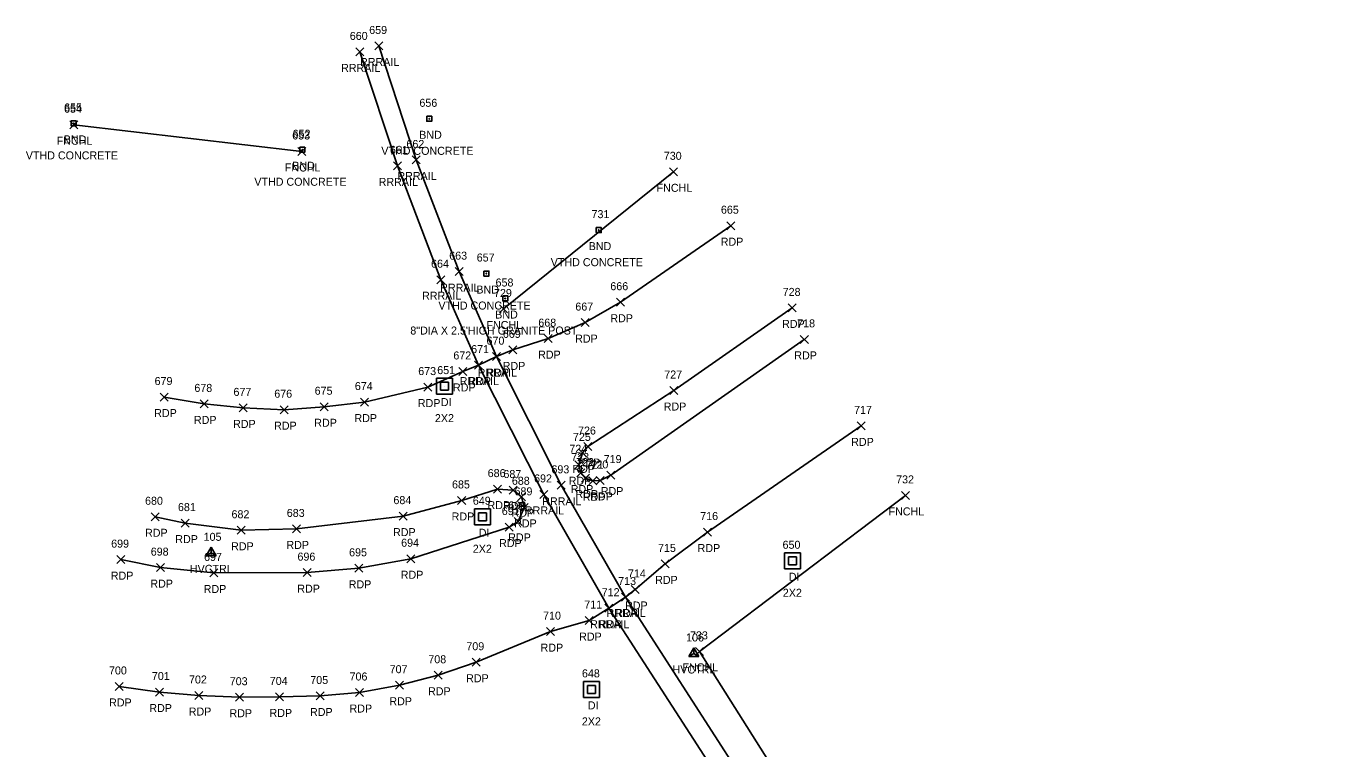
# Model space of a CAD drawing. Extents: x 1638029 to 1638889, y 618768 to 620505.
# Drawn here: x 1638029 to 1638352.1, y 620324.6 to 620505.1 of the extents above; entities that cross this region are included whole.
import ezdxf

# ---------------------------------------------------------------- set-up
doc = ezdxf.new("R2010")
doc.units = 0
for name, color, linetype in [('C_A', 7, 'Continuous'), ('C_I', 7, 'Continuous'), ('CPSM', 7, 'Continuous'), ('D_A', 7, 'Continuous'), ('D_C', 7, 'Continuous'), ('D_I', 7, 'Continuous'), ('DS', 7, 'Continuous'), ('L_A', 7, 'Continuous'), ('L_I', 7, 'Continuous'), ('L_TIC', 7, 'Continuous'), ('LFNC', 7, 'Continuous'), ('M_A', 7, 'Continuous'), ('M_C', 7, 'Continuous'), ('M_I', 7, 'Continuous'), ('MHBP', 7, 'Continuous'), ('P_A', 7, 'Continuous'), ('P_I', 7, 'Continuous'), ('P_TIC', 7, 'Continuous'), ('PET', 7, 'Continuous'), ('R_A', 7, 'Continuous'), ('R_I', 7, 'Continuous'), ('R_TIC', 7, 'Continuous'), ('RR', 7, 'Continuous')]:
    doc.layers.add(name, color=color, linetype=linetype)

msp = doc.modelspace()

# ---------------------------------------------------------------- linework, layer by layer
at = {"layer": 'CPSM'}
for p, q in [((1638074.04, 620372.66), (1638075.29, 620374.82)), ((1638074.04, 620372.66), (1638075.29, 620373.38)), ((1638076.54, 620372.66), (1638075.29, 620374.82)), ((1638075.29, 620373.38), (1638075.29, 620374.82)), ((1638075.29, 620373.38), (1638075.29, 620373.38)), ((1638075.29, 620373.38), (1638076.54, 620372.66)), ((1638074.04, 620372.66), (1638076.54, 620372.66)), ((1638194.63, 620347.51), (1638195.88, 620349.68)), ((1638194.63, 620347.51), (1638195.88, 620348.23)), ((1638194.63, 620347.51), (1638197.13, 620347.51)), ((1638197.13, 620347.51), (1638195.88, 620349.68)), ((1638195.88, 620348.23), (1638195.88, 620349.68)), ((1638195.88, 620348.23), (1638195.88, 620348.23)), ((1638195.88, 620348.23), (1638197.13, 620347.51))]:
    msp.add_line(p, q, dxfattribs=at)
at = {"layer": 'DS'}
for p, q in [((1638131.61, 620417.03), (1638135.61, 620417.03)), ((1638131.61, 620413.03), (1638131.61, 620417.03)), ((1638132.61, 620414.03), (1638132.61, 620416.03)), ((1638132.61, 620416.03), (1638134.61, 620416.03)), ((1638133.61, 620415.04), (1638133.61, 620415.04)), ((1638133.61, 620415.04), (1638133.61, 620415.04)), ((1638134.61, 620416.03), (1638134.61, 620414.03)), ((1638135.61, 620417.03), (1638135.61, 620413.03)), ((1638135.61, 620413.03), (1638131.61, 620413.03)), ((1638134.61, 620414.03), (1638132.61, 620414.03)), ((1638141.08, 620384.4), (1638145.08, 620384.4)), ((1638141.08, 620380.4), (1638141.08, 620384.4)), ((1638142.08, 620381.4), (1638142.08, 620383.4)), ((1638142.08, 620383.4), (1638144.08, 620383.4)), ((1638144.08, 620383.4), (1638144.08, 620381.4)), ((1638145.08, 620384.4), (1638145.08, 620380.4)), ((1638145.08, 620380.4), (1638141.08, 620380.4)), ((1638144.08, 620381.4), (1638142.08, 620381.4)), ((1638143.09, 620382.4), (1638143.09, 620382.4)), ((1638143.09, 620382.4), (1638143.09, 620382.4)), ((1638218.54, 620373.4), (1638222.54, 620373.4)), ((1638218.54, 620369.4), (1638218.54, 620373.4)), ((1638222.54, 620373.4), (1638222.54, 620369.4)), ((1638219.54, 620370.4), (1638219.54, 620372.4)), ((1638219.54, 620372.4), (1638221.54, 620372.4)), ((1638221.54, 620370.4), (1638219.54, 620370.4)), ((1638220.55, 620371.4), (1638220.55, 620371.4)), ((1638220.55, 620371.4), (1638220.55, 620371.4)), ((1638221.54, 620372.4), (1638221.54, 620370.4)), ((1638222.54, 620369.4), (1638218.54, 620369.4)), ((1638168.33, 620341.26), (1638172.33, 620341.26)), ((1638168.33, 620337.26), (1638168.33, 620341.26)), ((1638172.33, 620341.26), (1638172.33, 620337.26)), ((1638169.33, 620338.26), (1638169.33, 620340.26)), ((1638169.33, 620340.26), (1638171.33, 620340.26)), ((1638171.33, 620338.26), (1638169.33, 620338.26)), ((1638170.34, 620339.26), (1638170.34, 620339.26)), ((1638170.34, 620339.26), (1638170.34, 620339.26)), ((1638171.33, 620340.26), (1638171.33, 620338.26)), ((1638172.33, 620337.26), (1638168.33, 620337.26))]:
    msp.add_line(p, q, dxfattribs=at)
at = {"layer": 'L_TIC'}
for points in [[(1638039.95, 620479.35), (1638041.95, 620481.35)], [(1638041.95, 620479.35), (1638039.95, 620481.35)], [(1638096.95, 620472.67), (1638098.95, 620474.67)], [(1638098.95, 620472.67), (1638096.95, 620474.67)], [(1638189.83, 620467.59), (1638191.83, 620469.59)], [(1638191.83, 620467.59), (1638189.83, 620469.59)], [(1638147.32, 620433.31), (1638149.32, 620435.31)], [(1638149.32, 620433.31), (1638147.32, 620435.31)], [(1638247.78, 620386.73), (1638249.78, 620388.73)], [(1638249.78, 620386.73), (1638247.78, 620388.73)], [(1638196.3, 620347.76), (1638198.3, 620349.76)], [(1638198.3, 620347.76), (1638196.3, 620349.76)]]:
    msp.add_lwpolyline(points, dxfattribs=at)
at = {"layer": 'LFNC'}
for points in [[(1638097.95, 620473.67), (1638040.95, 620480.35)], [(1638148.32, 620434.31), (1638190.83, 620468.59)], [(1638248.78, 620387.73), (1638197.3, 620348.76), (1638216.93, 620317.58)]]:
    msp.add_lwpolyline(points, dxfattribs=at)
at = {"layer": 'MHBP'}
for points in [[(1638040.35, 620481.32), (1638041.6, 620481.32), (1638041.6, 620480.07), (1638040.35, 620480.07)], [(1638129.16, 620482.46), (1638130.41, 620482.46), (1638130.41, 620481.21), (1638129.16, 620481.21)], [(1638097.44, 620474.73), (1638098.69, 620474.73), (1638098.69, 620473.48), (1638097.44, 620473.48)], [(1638171.49, 620454.64), (1638172.74, 620454.64), (1638172.74, 620453.39), (1638171.49, 620453.39)], [(1638143.43, 620443.79), (1638144.68, 620443.79), (1638144.68, 620442.54), (1638143.43, 620442.54)], [(1638148.13, 620437.56), (1638149.38, 620437.56), (1638149.38, 620436.31), (1638148.13, 620436.31)]]:
    msp.add_lwpolyline(points, close=True, dxfattribs=at)
for centre in [(1638040.97, 620480.69), (1638129.78, 620481.83), (1638098.06, 620474.1), (1638172.12, 620454.01), (1638144.05, 620443.17), (1638148.76, 620436.93)]:
    msp.add_circle(centre, 0.0833, dxfattribs=at)
at = {"layer": 'P_TIC'}
for points in [[(1638204.11, 620454.12), (1638206.11, 620456.12)], [(1638206.11, 620454.12), (1638204.11, 620456.12)], [(1638176.53, 620435), (1638178.53, 620437)], [(1638178.53, 620435), (1638176.53, 620437)], [(1638219.44, 620433.58), (1638221.44, 620435.58)], [(1638221.44, 620433.58), (1638219.44, 620435.58)], [(1638167.74, 620429.91), (1638169.74, 620431.91)], [(1638169.74, 620429.91), (1638167.74, 620431.91)], [(1638158.49, 620425.9), (1638160.49, 620427.9)], [(1638160.49, 620425.9), (1638158.49, 620427.9)], [(1638149.63, 620423.09), (1638151.63, 620425.09)], [(1638151.63, 620423.09), (1638149.63, 620425.09)], [(1638222.49, 620425.72), (1638224.49, 620427.72)], [(1638224.49, 620425.72), (1638222.49, 620427.72)], [(1638145.58, 620421.4), (1638147.58, 620423.4)], [(1638147.58, 620421.4), (1638145.58, 620423.4)], [(1638137.21, 620417.7), (1638139.21, 620419.7)], [(1638139.21, 620417.7), (1638137.21, 620419.7)], [(1638141.09, 620419.29), (1638143.09, 620421.29)], [(1638143.09, 620419.29), (1638141.09, 620421.29)], [(1638128.44, 620413.8), (1638130.44, 620415.8)], [(1638130.44, 620413.8), (1638128.44, 620415.8)], [(1638189.86, 620412.94), (1638191.86, 620414.94)], [(1638191.86, 620412.94), (1638189.86, 620414.94)], [(1638062.58, 620411.31), (1638064.58, 620413.31)], [(1638064.58, 620411.31), (1638062.58, 620413.31)], [(1638112.6, 620410.05), (1638114.6, 620412.05)], [(1638114.6, 620410.05), (1638112.6, 620412.05)], [(1638072.51, 620409.59), (1638074.51, 620411.59)], [(1638074.51, 620409.59), (1638072.51, 620411.59)], [(1638082.28, 620408.59), (1638084.28, 620410.59)], [(1638084.28, 620408.59), (1638082.28, 620410.59)], [(1638092.53, 620408.15), (1638094.53, 620410.15)], [(1638094.53, 620408.15), (1638092.53, 620410.15)], [(1638102.56, 620408.88), (1638104.56, 620410.88)], [(1638104.56, 620408.88), (1638102.56, 620410.88)], [(1638236.72, 620404.1), (1638238.72, 620406.1)], [(1638238.72, 620404.1), (1638236.72, 620406.1)], [(1638167.04, 620397.35), (1638169.04, 620399.35)], [(1638169.04, 620397.35), (1638167.04, 620399.35)], [(1638168.36, 620398.93), (1638170.36, 620400.93)], [(1638170.36, 620398.93), (1638168.36, 620400.93)], [(1638166.14, 620394.39), (1638168.14, 620396.39)], [(1638168.14, 620394.39), (1638166.14, 620396.39)], [(1638166.62, 620392.33), (1638168.62, 620394.33)], [(1638168.62, 620392.33), (1638166.62, 620394.33)], [(1638167.82, 620391.05), (1638169.82, 620393.05)], [(1638169.82, 620391.05), (1638167.82, 620393.05)], [(1638169.64, 620390.38), (1638171.64, 620392.38)], [(1638171.64, 620390.38), (1638169.64, 620392.38)], [(1638171.5, 620390.48), (1638173.5, 620392.48)], [(1638173.5, 620390.48), (1638171.5, 620392.48)], [(1638174.15, 620391.81), (1638176.15, 620393.81)], [(1638176.15, 620391.81), (1638174.15, 620393.81)], [(1638145.85, 620388.3), (1638147.85, 620390.3)], [(1638147.85, 620388.3), (1638145.85, 620390.3)], [(1638149.72, 620388.08), (1638151.72, 620390.08)], [(1638151.72, 620388.08), (1638149.72, 620390.08)], [(1638136.88, 620385.47), (1638138.88, 620387.47)], [(1638138.88, 620385.47), (1638136.88, 620387.47)], [(1638151.83, 620386.38), (1638153.83, 620388.38)], [(1638153.83, 620386.38), (1638151.83, 620388.38)], [(1638060.28, 620381.39), (1638062.28, 620383.39)], [(1638062.28, 620381.39), (1638060.28, 620383.39)], [(1638122.24, 620381.55), (1638124.24, 620383.55)], [(1638124.24, 620381.55), (1638122.24, 620383.55)], [(1638152.5, 620383.74), (1638154.5, 620385.74)], [(1638154.5, 620383.74), (1638152.5, 620385.74)], [(1638067.84, 620379.81), (1638069.84, 620381.81)], [(1638069.84, 620379.81), (1638067.84, 620381.81)], [(1638081.79, 620378.02), (1638083.79, 620380.02)], [(1638083.79, 620378.02), (1638081.79, 620380.02)], [(1638095.6, 620378.35), (1638097.6, 620380.35)], [(1638097.6, 620378.35), (1638095.6, 620380.35)], [(1638148.74, 620378.82), (1638150.74, 620380.82)], [(1638150.74, 620378.82), (1638148.74, 620380.82)], [(1638151.02, 620380.24), (1638153.02, 620382.24)], [(1638153.02, 620380.24), (1638151.02, 620382.24)], [(1638198.33, 620377.57), (1638200.33, 620379.57)], [(1638200.33, 620377.57), (1638198.33, 620379.57)], [(1638051.73, 620370.68), (1638053.73, 620372.68)], [(1638053.73, 620370.68), (1638051.73, 620372.68)], [(1638061.61, 620368.68), (1638063.61, 620370.68)], [(1638063.61, 620368.68), (1638061.61, 620370.68)], [(1638111.17, 620368.51), (1638113.17, 620370.51)], [(1638113.17, 620368.51), (1638111.17, 620370.51)], [(1638124.17, 620370.9), (1638126.17, 620372.9)], [(1638126.17, 620370.9), (1638124.17, 620372.9)], [(1638187.74, 620369.61), (1638189.74, 620371.61)], [(1638189.74, 620369.61), (1638187.74, 620371.61)], [(1638074.93, 620367.35), (1638076.93, 620369.35)], [(1638076.93, 620367.35), (1638074.93, 620369.35)], [(1638098.32, 620367.43), (1638100.32, 620369.43)], [(1638100.32, 620367.43), (1638098.32, 620369.43)], [(1638177.78, 620361.34), (1638179.78, 620363.34)], [(1638179.78, 620361.34), (1638177.78, 620363.34)], [(1638180.21, 620363.22), (1638182.21, 620365.22)], [(1638182.21, 620363.22), (1638180.21, 620365.22)], [(1638173.67, 620358.55), (1638175.67, 620360.55)], [(1638175.67, 620358.55), (1638173.67, 620360.55)], [(1638168.74, 620355.45), (1638170.74, 620357.45)], [(1638170.74, 620355.45), (1638168.74, 620357.45)], [(1638159.1, 620352.69), (1638161.1, 620354.69)], [(1638161.1, 620352.69), (1638159.1, 620354.69)], [(1638140.5, 620345.04), (1638142.5, 620347.04)], [(1638142.5, 620345.04), (1638140.5, 620347.04)], [(1638051.3, 620338.99), (1638053.3, 620340.99)], [(1638053.3, 620338.99), (1638051.3, 620340.99)], [(1638121.32, 620339.3), (1638123.32, 620341.3)], [(1638123.32, 620339.3), (1638121.32, 620341.3)], [(1638130.99, 620341.79), (1638132.99, 620343.79)], [(1638132.99, 620341.79), (1638130.99, 620343.79)], [(1638061.35, 620337.6), (1638063.35, 620339.6)], [(1638063.35, 620337.6), (1638061.35, 620339.6)], [(1638071.2, 620336.73), (1638073.2, 620338.73)], [(1638073.2, 620336.73), (1638071.2, 620338.73)], [(1638081.38, 620336.3), (1638083.38, 620338.3)], [(1638083.38, 620336.3), (1638081.38, 620338.3)], [(1638091.38, 620336.37), (1638093.38, 620338.37)], [(1638093.38, 620336.37), (1638091.38, 620338.37)], [(1638101.5, 620336.61), (1638103.5, 620338.61)], [(1638103.5, 620336.61), (1638101.5, 620338.61)], [(1638111.37, 620337.48), (1638113.37, 620339.48)], [(1638113.37, 620337.48), (1638111.37, 620339.48)]]:
    msp.add_lwpolyline(points, dxfattribs=at)
at = {"layer": 'PET'}
for points in [[(1638205.11, 620455.12), (1638177.53, 620436), (1638168.74, 620430.91), (1638159.49, 620426.9), (1638150.63, 620424.09), (1638146.58, 620422.4), (1638142.09, 620420.29), (1638138.21, 620418.7), (1638129.44, 620414.8), (1638113.6, 620411.05), (1638103.56, 620409.88), (1638093.53, 620409.15), (1638083.28, 620409.59), (1638073.51, 620410.59), (1638063.58, 620412.31)], [(1638223.49, 620426.72), (1638175.15, 620392.81), (1638172.5, 620391.48), (1638170.64, 620391.38), (1638168.82, 620392.05), (1638167.62, 620393.33), (1638167.14, 620395.39), (1638168.04, 620398.35), (1638169.36, 620399.93), (1638190.86, 620413.94), (1638220.44, 620434.58)], [(1638052.3, 620339.99), (1638062.35, 620338.6), (1638072.2, 620337.73), (1638082.38, 620337.3), (1638092.38, 620337.37), (1638102.5, 620337.61), (1638112.37, 620338.48), (1638122.32, 620340.3), (1638131.99, 620342.79), (1638141.5, 620346.04), (1638160.1, 620353.69), (1638169.74, 620356.45), (1638174.67, 620359.55), (1638178.78, 620362.34), (1638181.21, 620364.22), (1638188.74, 620370.61), (1638199.33, 620378.57), (1638237.72, 620405.1)], [(1638061.28, 620382.39), (1638068.84, 620380.81), (1638082.79, 620379.02), (1638096.6, 620379.35), (1638123.24, 620382.55), (1638137.88, 620386.47), (1638146.85, 620389.3), (1638150.72, 620389.08), (1638152.83, 620387.38), (1638153.5, 620384.74), (1638152.02, 620381.24), (1638149.74, 620379.82), (1638125.17, 620371.9), (1638112.17, 620369.51), (1638099.32, 620368.43), (1638075.93, 620368.35), (1638062.61, 620369.68), (1638052.73, 620371.68)]]:
    msp.add_lwpolyline(points, dxfattribs=at)
at = {"layer": 'R_TIC'}
for points in [[(1638111.47, 620497.54), (1638113.47, 620499.54)], [(1638113.47, 620497.54), (1638111.47, 620499.54)], [(1638116.2, 620499.03), (1638118.2, 620501.03)], [(1638118.2, 620499.03), (1638116.2, 620501.03)], [(1638120.85, 620469.07), (1638122.85, 620471.07)], [(1638122.85, 620469.07), (1638120.85, 620471.07)], [(1638125.53, 620470.54), (1638127.53, 620472.54)], [(1638127.53, 620470.54), (1638125.53, 620472.54)], [(1638136.23, 620442.64), (1638138.23, 620444.64)], [(1638138.23, 620442.64), (1638136.23, 620444.64)], [(1638131.7, 620440.63), (1638133.7, 620442.63)], [(1638133.7, 620440.63), (1638131.7, 620442.63)], [(1638145.58, 620421.4), (1638147.58, 620423.4)], [(1638147.58, 620421.4), (1638145.58, 620423.4)], [(1638141.09, 620419.29), (1638143.09, 620421.29)], [(1638143.09, 620419.29), (1638141.09, 620421.29)], [(1638161.72, 620389.25), (1638163.72, 620391.25)], [(1638163.72, 620389.25), (1638161.72, 620391.25)], [(1638157.38, 620386.98), (1638159.38, 620388.98)], [(1638159.38, 620386.98), (1638157.38, 620388.98)], [(1638177.78, 620361.34), (1638179.78, 620363.34)], [(1638179.78, 620361.34), (1638177.78, 620363.34)], [(1638173.67, 620358.55), (1638175.67, 620360.55)], [(1638175.67, 620358.55), (1638173.67, 620360.55)]]:
    msp.add_lwpolyline(points, dxfattribs=at)
at = {"layer": 'RR'}
for points in [[(1638117.2, 620500.03), (1638126.53, 620471.54), (1638137.23, 620443.64), (1638146.58, 620422.4), (1638162.72, 620390.25), (1638178.78, 620362.34), (1638206.73, 620318.99), (1638221.73, 620298.51), (1638231.34, 620286.06), (1638247.72, 620265.63), (1638271.6, 620237.56), (1638302.87, 620202.63), (1638319.77, 620183.84), (1638340.9, 620160.55), (1638398.39, 620097.17), (1638473.27, 620014.71), (1638530.28, 619952.03), (1638576.7, 619900.87), (1638602.43, 619872.23), (1638628.75, 619841.68), (1638648.78, 619815.3)], [(1638112.47, 620498.54), (1638121.85, 620470.07), (1638132.7, 620441.63), (1638142.09, 620420.29), (1638158.38, 620387.98), (1638174.67, 620359.55), (1638202.82, 620316.02), (1638218.22, 620294.92), (1638227.34, 620283.09), (1638243.87, 620262.45), (1638266.59, 620235.71), (1638298.84, 620199.7), (1638316.08, 620180.56), (1638337.37, 620157.11), (1638394.65, 620093.98), (1638469.89, 620011.06), (1638526.76, 619948.51), (1638573.25, 619897.28), (1638598.73, 619868.77), (1638625.03, 619838.36), (1638644.96, 619812.19)]]:
    msp.add_lwpolyline(points, dxfattribs=at)

# ---------------------------------------------------------------- texts
at = {"layer": 'C_A'}
for p in [(1638069.98, 620368.38), (1638190.57, 620343.23)]:
    msp.add_text('HVCTRL', height=2, dxfattribs=at).set_placement(p)
at = {"layer": 'C_I'}
for s, p in [('105', (1638073.41, 620376.38)), ('106', (1638193.95, 620351.23))]:
    msp.add_text(s, height=2, dxfattribs=at).set_placement(p)
at = {"layer": 'D_A'}
for p in [(1638132.67, 620410.04), (1638142.14, 620377.4), (1638219.6, 620366.4), (1638169.39, 620334.26)]:
    msp.add_text('DI', height=2, dxfattribs=at).set_placement(p)
at = {"layer": 'D_C'}
for p in [(1638131.19, 620406.04), (1638140.66, 620373.4), (1638218.12, 620362.4), (1638167.91, 620330.26)]:
    msp.add_text('2X2', height=2, dxfattribs=at).set_placement(p)
at = {"layer": 'D_I'}
for s, p in [('651', (1638131.77, 620418.04)), ('649', (1638140.67, 620385.4)), ('650', (1638218.05, 620374.4)), ('648', (1638167.93, 620342.26))]:
    msp.add_text(s, height=2, dxfattribs=at).set_placement(p)
at = {"layer": 'L_A'}
for p in [(1638036.7, 620475.35), (1638093.7, 620468.67), (1638186.58, 620463.59), (1638144.07, 620429.31), (1638244.53, 620382.73), (1638193.04, 620343.76)]:
    msp.add_text('FNCHL', height=2, dxfattribs=at).set_placement(p)
at = {"layer": 'L_I'}
for s, p in [('654', (1638038.54, 620483.35)), ('653', (1638095.54, 620476.67)), ('730', (1638188.38, 620471.59)), ('729', (1638145.95, 620437.31)), ('732', (1638246.42, 620390.73)), ('733', (1638194.93, 620351.76))]:
    msp.add_text(s, height=2, dxfattribs=at).set_placement(p)
at = {"layer": 'M_A'}
for p in [(1638038.46, 620475.69), (1638127.27, 620476.83), (1638095.55, 620469.1), (1638169.61, 620449.01), (1638141.54, 620438.17), (1638146.25, 620431.93)]:
    msp.add_text('BND', height=2, dxfattribs=at).set_placement(p)
at = {"layer": 'M_C'}
for s, p in [('VTHD CONCRETE', (1638028.99, 620471.69)), ('VTHD CONCRETE', (1638117.8, 620472.83)), ('VTHD CONCRETE', (1638086.08, 620465.1)), ('VTHD CONCRETE', (1638160.13, 620445.01)), ('VTHD CONCRETE', (1638132.07, 620434.17)), ('8"DIA X 2.5\'HIGH GRANITE POST', (1638125.05, 620427.93))]:
    msp.add_text(s, height=2, dxfattribs=at).set_placement(p)
at = {"layer": 'M_I'}
for s, p in [('656', (1638127.32, 620484.83)), ('655', (1638038.56, 620483.69)), ('652', (1638095.65, 620477.1)), ('731', (1638170.32, 620457.01)), ('657', (1638141.64, 620446.17)), ('658', (1638146.35, 620439.93))]:
    msp.add_text(s, height=2, dxfattribs=at).set_placement(p)
at = {"layer": 'P_A'}
for p in [(1638202.6, 620450.12), (1638175.02, 620431), (1638217.93, 620429.58), (1638166.23, 620425.91), (1638156.98, 620421.9), (1638220.98, 620421.72), (1638144.07, 620417.4), (1638148.12, 620419.09), (1638135.7, 620413.7), (1638139.58, 620415.29), (1638126.93, 620409.8), (1638061.06, 620407.31), (1638188.35, 620408.94), (1638070.99, 620405.59), (1638080.77, 620404.59), (1638091.02, 620404.15), (1638101.05, 620404.88), (1638111.09, 620406.05), (1638235.2, 620400.1), (1638166.85, 620394.93), (1638164.63, 620390.39), (1638165.53, 620393.35), (1638165.11, 620388.33), (1638172.64, 620387.81), (1638144.34, 620384.3), (1638148.21, 620384.08), (1638166.31, 620387.05), (1638168.13, 620386.38), (1638169.99, 620386.48), (1638135.37, 620381.47), (1638150.32, 620382.38), (1638058.77, 620377.39), (1638120.73, 620377.55), (1638150.99, 620379.74), (1638066.33, 620375.81), (1638094.09, 620374.35), (1638147.23, 620374.82), (1638149.51, 620376.24), (1638080.27, 620374.02), (1638196.82, 620373.57), (1638050.22, 620366.68), (1638060.1, 620364.68), (1638109.66, 620364.51), (1638122.66, 620366.9), (1638186.22, 620365.61), (1638073.42, 620363.35), (1638096.81, 620363.43), (1638178.7, 620359.22), (1638176.27, 620357.34), (1638172.16, 620354.55), (1638157.59, 620348.69), (1638167.23, 620351.45), (1638138.99, 620341.04), (1638129.48, 620337.79), (1638049.79, 620334.99), (1638059.84, 620333.6), (1638069.69, 620332.73), (1638079.87, 620332.3), (1638089.87, 620332.37), (1638099.99, 620332.61), (1638109.86, 620333.48), (1638119.81, 620335.3)]:
    msp.add_text('RDP', height=2, dxfattribs=at).set_placement(p)
at = {"layer": 'P_I'}
for s, p in [('665', (1638202.65, 620458.12)), ('666', (1638175.02, 620439)), ('728', (1638218.08, 620437.58)), ('667', (1638166.28, 620433.91)), ('668', (1638157.03, 620429.9)), ('718', (1638221.7, 620429.72)), ('669', (1638148.17, 620427.09)), ('671', (1638140.25, 620423.29)), ('670', (1638144.09, 620425.4)), ('672', (1638135.8, 620421.7)), ('673', (1638127.03, 620417.8)), ('727', (1638188.5, 620416.94)), ('679', (1638061.16, 620415.31)), ('678', (1638071.1, 620413.59)), ('674', (1638111.19, 620414.05)), ('677', (1638080.87, 620412.59)), ('676', (1638091.06, 620412.15)), ('675', (1638101.15, 620412.88)), ('717', (1638235.92, 620408.1)), ('725', (1638165.68, 620401.35)), ('726', (1638166.95, 620402.93)), ('724', (1638164.78, 620398.39)), ('723', (1638165.26, 620396.33)), ('722', (1638166.46, 620395.05)), ('721', (1638168.85, 620394.38)), ('720', (1638170.05, 620394.48)), ('719', (1638173.35, 620395.81)), ('686', (1638144.38, 620392.3)), ('687', (1638148.31, 620392.08)), ('688', (1638150.42, 620390.38)), ('685', (1638135.47, 620389.47)), ('689', (1638151.09, 620387.74)), ('680', (1638058.78, 620385.39)), ('684', (1638120.83, 620385.55)), ('690', (1638149.53, 620384.24)), ('681', (1638067, 620383.81)), ('682', (1638080.38, 620382.02)), ('683', (1638094.19, 620382.35)), ('691', (1638147.9, 620382.82)), ('716', (1638197.48, 620381.57)), ('699', (1638050.31, 620374.68)), ('694', (1638122.76, 620374.9)), ('698', (1638060.2, 620372.68)), ('697', (1638073.52, 620371.35)), ('696', (1638096.86, 620371.43)), ('695', (1638109.76, 620372.51)), ('715', (1638186.94, 620373.61)), ('713', (1638176.98, 620365.34)), ('714', (1638179.42, 620367.22)), ('712', (1638172.87, 620362.55)), ('711', (1638168.51, 620359.45)), ('710', (1638158.22, 620356.69)), ('709', (1638139.05, 620349.04)), ('708', (1638129.55, 620345.79)), ('700', (1638049.77, 620342.99)), ('707', (1638119.88, 620343.3)), ('701', (1638060.48, 620341.6)), ('702', (1638069.76, 620340.73)), ('703', (1638079.94, 620340.3)), ('704', (1638089.94, 620340.37)), ('705', (1638100.06, 620340.61)), ('706', (1638109.87, 620341.48))]:
    msp.add_text(s, height=2, dxfattribs=at).set_placement(p)
at = {"layer": 'R_A'}
for p in [(1638112.49, 620495.03), (1638107.76, 620493.54), (1638117.14, 620465.07), (1638121.82, 620466.54), (1638127.99, 620436.63), (1638132.52, 620438.64), (1638141.88, 620417.4), (1638137.38, 620415.29), (1638158.01, 620385.25), (1638153.67, 620382.98), (1638174.07, 620357.34), (1638169.96, 620354.55)]:
    msp.add_text('RRRAIL', height=2, dxfattribs=at).set_placement(p)
at = {"layer": 'R_I'}
for s, p in [('660', (1638109.93, 620501.54)), ('659', (1638114.78, 620503.03)), ('662', (1638124.08, 620474.54)), ('661', (1638119.96, 620473.07)), ('663', (1638134.77, 620446.64)), ('664', (1638130.24, 620444.63)), ('671', (1638140.25, 620423.29)), ('670', (1638144.09, 620425.4)), ('692', (1638155.97, 620390.98)), ('693', (1638160.31, 620393.25)), ('713', (1638176.98, 620365.34)), ('712', (1638172.87, 620362.55))]:
    msp.add_text(s, height=2, dxfattribs=at).set_placement(p)

doc.saveas('drawing.dxf')
